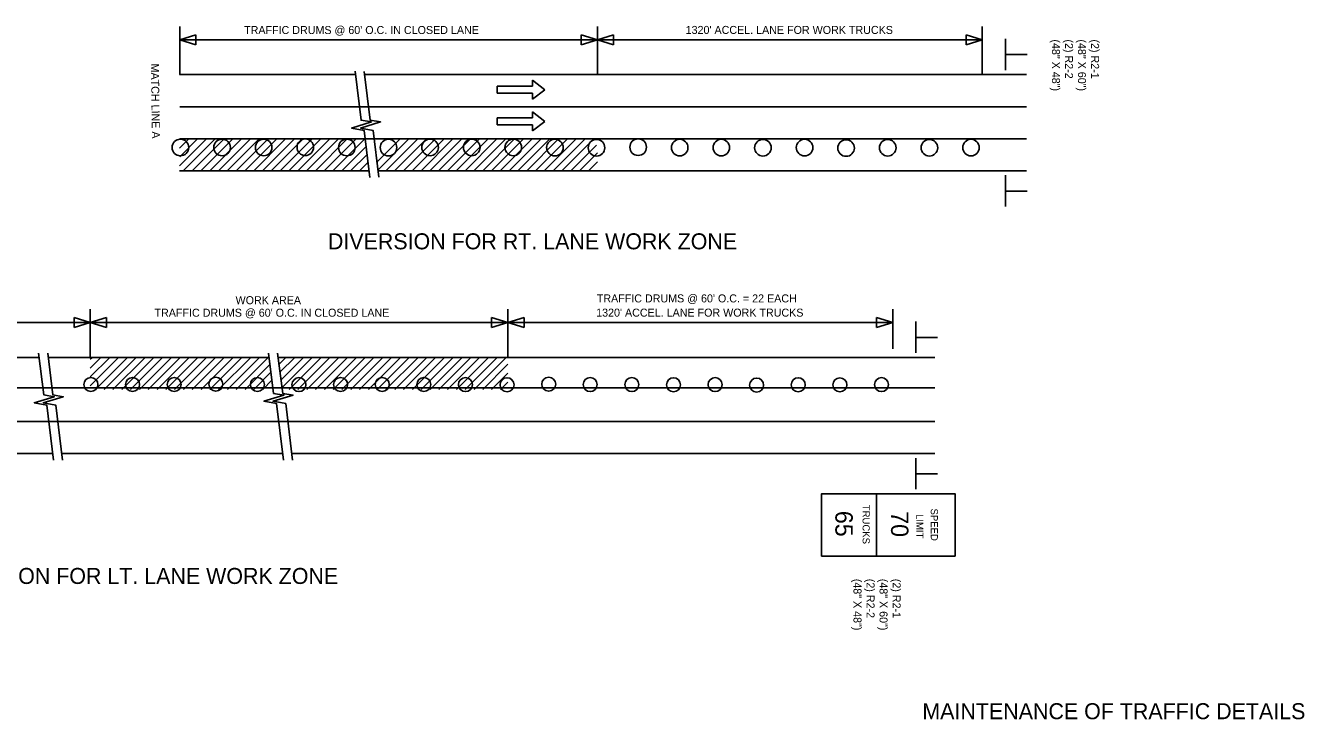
# Model space of a CAD drawing. Extents: x 37171 to 39457, y -18939 to -17445.
# Drawn here: x 38020 to 39457, y -18939 to -18159 of the extents above; entities that cross this region are included whole.
import ezdxf

# ---------------------------------------------------------------- set-up
doc = ezdxf.new("R2010")
doc.units = 0
for name, color, linetype in [('Default', 7, 'Continuous'), ('R_Border', 7, 'Continuous'), ('R_Const Phase 4', 7, 'Continuous'), ('R_Proposed Road Annot', 7, 'Continuous')]:
    doc.layers.add(name, color=color, linetype=linetype)

msp = doc.modelspace()

# ---------------------------------------------------------------- linework, layer by layer
at = {"layer": 'Default'}
for p, q in [((38192.6, -18316.3), (38222.8, -18286.1)), ((38192.7, -18286.5), (38193.1, -18286.1)), ((38192.7, -18296.4), (38203, -18286.1)), ((38192.9, -18306.1), (38212.9, -18286.1)), ((38196.8, -18321.9), (38232.7, -18286.1)), ((38206.7, -18321.9), (38242.6, -18286.1)), ((38216.6, -18321.9), (38252.5, -18286.1)), ((38226.5, -18321.9), (38262.4, -18286.1)), ((38236.4, -18321.9), (38272.3, -18286.1)), ((38246.3, -18321.9), (38282.2, -18286.1)), ((38256.2, -18321.9), (38292.1, -18286.1)), ((38266.1, -18321.9), (38302, -18286.1)), ((38276, -18321.9), (38311.9, -18286.1)), ((38285.9, -18321.9), (38321.8, -18286.1)), ((38295.8, -18321.9), (38331.7, -18286.1)), ((38305.7, -18321.9), (38341.6, -18286.1)), ((38315.6, -18321.9), (38351.5, -18286.1)), ((38325.5, -18321.9), (38361.4, -18286.1)), ((38335.4, -18321.9), (38371.3, -18286.1)), ((38345.3, -18321.9), (38381.2, -18286.1)), ((38355.2, -18321.9), (38391.1, -18286.1)), ((38365.1, -18321.9), (38401.3, -18285.7)), ((38413.9, -18312.7), (38440.6, -18286.1)), ((38415, -18321.6), (38450.5, -18286.1)), ((38424.5, -18321.9), (38460.4, -18286.1)), ((38434.4, -18321.9), (38470.3, -18286.1)), ((38444.3, -18321.9), (38480.2, -18286.1)), ((38454.2, -18321.9), (38490.1, -18286.1)), ((38464.1, -18321.9), (38500, -18286.1)), ((38474, -18321.9), (38509.9, -18286.1)), ((38483.9, -18321.9), (38519.8, -18286.1)), ((38493.8, -18321.9), (38529.7, -18286.1)), ((38503.7, -18321.9), (38539.6, -18286.1)), ((38513.6, -18321.9), (38549.5, -18286.1)), ((38523.5, -18321.9), (38559.4, -18286.1)), ((38533.4, -18321.9), (38569.3, -18286.1)), ((38543.3, -18321.9), (38579.2, -18286.1)), ((38553.2, -18321.9), (38589.1, -18286.1)), ((38563.1, -18321.9), (38599, -18286.1)), ((38573, -18321.9), (38608.9, -18286.1)), ((38582.9, -18321.9), (38618.8, -18286.1)), ((38592.8, -18321.9), (38628.7, -18286.1)), ((38602.7, -18321.9), (38638.6, -18286.1)), ((38612.6, -18321.9), (38648.5, -18286.1)), ((38622.5, -18321.9), (38658.4, -18286.1)), ((38375, -18321.9), (38402.4, -18294.6)), ((38632.4, -18321.9), (38661.3, -18293)), ((38642.3, -18321.9), (38662.4, -18301.8)), ((38384.9, -18321.9), (38403.5, -18303.4)), ((38394.8, -18321.9), (38404.5, -18312.2)), ((38652.2, -18321.9), (38662.4, -18311.8)), ((38092.3, -18563.6), (38124.1, -18531.7)), ((38092.3, -18553.7), (38114.2, -18531.7)), ((38092.3, -18543.8), (38104.3, -18531.7)), ((38092.3, -18533.9), (38094.4, -18531.7)), ((38098, -18567.7), (38134, -18531.7)), ((38107.9, -18567.7), (38143.9, -18531.7)), ((38117.8, -18567.7), (38153.8, -18531.7)), ((38127.7, -18567.7), (38163.7, -18531.7)), ((38137.6, -18567.7), (38173.6, -18531.7)), ((38147.5, -18567.7), (38183.5, -18531.7)), ((38157.4, -18567.7), (38193.4, -18531.7)), ((38167.3, -18567.7), (38203.3, -18531.7)), ((38177.2, -18567.7), (38213.2, -18531.7)), ((38187.1, -18567.7), (38223.1, -18531.7)), ((38197, -18567.7), (38233, -18531.7)), ((38206.9, -18567.7), (38242.9, -18531.7)), ((38216.8, -18567.7), (38252.8, -18531.7)), ((38226.7, -18567.7), (38262.7, -18531.7)), ((38236.6, -18567.7), (38272.6, -18531.7)), ((38246.5, -18567.7), (38282.5, -18531.7)), ((38256.4, -18567.7), (38292.4, -18531.7)), ((38304.5, -18539.4), (38312.2, -18531.7)), ((38305.8, -18548), (38322.1, -18531.7)), ((38306.8, -18556.9), (38332, -18531.7)), ((38307.9, -18565.7), (38341.9, -18531.7)), ((38315.8, -18567.7), (38351.8, -18531.7)), ((38325.7, -18567.7), (38361.7, -18531.7)), ((38335.6, -18567.7), (38371.6, -18531.7)), ((38345.5, -18567.7), (38381.5, -18531.7)), ((38355.4, -18567.7), (38391.4, -18531.7)), ((38365.3, -18567.7), (38401.3, -18531.7)), ((38375.2, -18567.7), (38411.2, -18531.7)), ((38385.1, -18567.7), (38421.1, -18531.7)), ((38395, -18567.7), (38431, -18531.7)), ((38404.9, -18567.7), (38440.9, -18531.7)), ((38414.8, -18567.7), (38450.8, -18531.7)), ((38424.7, -18567.7), (38460.7, -18531.7)), ((38434.6, -18567.7), (38470.6, -18531.7)), ((38444.5, -18567.7), (38480.5, -18531.7)), ((38454.4, -18567.7), (38490.4, -18531.7)), ((38464.3, -18567.7), (38500.3, -18531.7)), ((38474.2, -18567.7), (38510.2, -18531.7)), ((38484.1, -18567.7), (38520.1, -18531.7)), ((38494, -18567.7), (38530, -18531.7)), ((38503.9, -18567.7), (38539.9, -18531.7)), ((38513.8, -18567.7), (38549.8, -18531.7)), ((38523.7, -18567.7), (38559.7, -18531.7)), ((38266.3, -18567.7), (38294.3, -18539.7)), ((38533.6, -18567.7), (38561.7, -18539.5)), ((38276.2, -18567.7), (38295.4, -18548.5)), ((38286.1, -18567.7), (38296.7, -18557.1)), ((38543.5, -18567.9), (38561.7, -18549.6)), ((38553.3, -18567.9), (38561.7, -18559.5))]:
    msp.add_line(p, q, dxfattribs=at)
for points in [[(38976.2, -18755.1), (38914.5, -18755.1), (38914.5, -18685.1), (38976.2, -18685.1)], [(39064.5, -18755.1), (38976.2, -18755.1), (38976.2, -18685.1), (39064.5, -18685.1)]]:
    msp.add_lwpolyline(points, close=True, dxfattribs=at)
for centre, radius in [((38193.6, -18295.7), 9.33), ((38240.4, -18295.7), 9.33), ((38287.2, -18295.7), 9.33), ((38334, -18295.4), 9.33), ((38380.7, -18295.7), 9.33), ((38427.5, -18295.8), 9.33), ((38474.3, -18295.6), 9.33), ((38521.1, -18295.6), 9.33), ((38567.8, -18295.6), 9.33), ((38614.6, -18295.8), 9.33), ((38661.4, -18296), 9.33), ((38708.2, -18295.3), 9.33), ((38754.9, -18295.8), 9.33), ((38801.7, -18295.8), 9.33), ((38848.5, -18296), 9.33), ((38895.3, -18295.8), 9.33), ((38942, -18296.3), 9.33), ((38988.8, -18296), 9.33), ((39035.6, -18296), 9.33), ((39082.4, -18295.8), 9.33), ((38093, -18562.2), 7.87), ((38139.8, -18562.2), 7.87), ((38186.6, -18562.2), 7.87), ((38233.4, -18561.9), 7.87), ((38280.1, -18562.2), 7.87), ((38326.9, -18562.4), 7.87), ((38373.7, -18562.2), 7.87), ((38420.5, -18562.2), 7.87), ((38467.2, -18562.2), 7.87), ((38514, -18562.4), 7.87), ((38560.8, -18562.5), 7.87), ((38607.6, -18561.9), 7.87), ((38654.3, -18562.3), 7.87), ((38701.1, -18562.3), 7.87), ((38747.9, -18562.5), 7.87), ((38794.7, -18562.4), 7.87), ((38841.4, -18562.9), 7.87), ((38888.2, -18562.5), 7.87), ((38935, -18562.6), 7.87), ((38981.8, -18562.4), 7.87)]:
    msp.add_circle(centre, radius, dxfattribs=at)
at = {"layer": 'R_Const Phase 4'}
for p, q in [((39121, -18208.8), (39121, -18173.6)), ((39121.5, -18191.3), (39145.5, -18191.3)), ((38192.6, -18213.8), (38390.4, -18213.8)), ((38400.6, -18213.8), (38662.4, -18213.8)), ((38662.4, -18213.8), (39144.7, -18213.8)), ((38589.3, -18226.7), (38549.8, -18226.7)), ((38549.8, -18226.7), (38549.8, -18234.7)), ((38589.3, -18220), (38589.3, -18226.7)), ((38589.3, -18220), (38603.2, -18230.7)), ((38589.3, -18234.7), (38549.8, -18234.7)), ((38603.2, -18230.7), (38589.3, -18241.5)), ((38589.3, -18234.7), (38589.3, -18241.5)), ((38192.9, -18249.9), (39144.7, -18249.9)), ((38589.3, -18255.5), (38589.3, -18262.2)), ((38589.3, -18255.5), (38603.2, -18266.3)), ((38589.3, -18262.2), (38549.8, -18262.2)), ((38549.8, -18262.2), (38549.8, -18270.3)), ((38589.3, -18270.3), (38549.8, -18270.3)), ((38603.2, -18266.3), (38589.3, -18277)), ((38589.3, -18270.3), (38589.3, -18277)), ((38192.9, -18286.1), (39144.7, -18286.1)), ((38192.6, -18321.9), (38405.7, -18321.9)), ((38415, -18321.9), (38662.4, -18321.9)), ((38662.4, -18321.9), (39144.7, -18321.9)), ((39121, -18362.2), (39121, -18326.9)), ((39121.5, -18344.7), (39145.5, -18344.7)), ((39020.4, -18526.7), (39020.4, -18491.5)), ((39020.9, -18509.2), (39044.9, -18509.2)), ((37659.5, -18531.7), (38034.8, -18531.7)), ((38045, -18531.7), (38092.3, -18531.7)), ((38092.3, -18531.7), (38293.4, -18531.7)), ((38303.6, -18531.7), (38561.7, -18531.7)), ((38561.7, -18531.7), (39041.7, -18531.7)), ((37294.7, -18566), (39041.7, -18566)), ((37294.7, -18603.9), (39041.7, -18603.9)), ((37659.5, -18639.9), (38050, -18639.9)), ((38060.2, -18639.9), (38092.3, -18639.9)), ((38092.3, -18639.9), (38308.6, -18639.9)), ((38318.8, -18639.9), (38561.7, -18639.9)), ((38561.7, -18639.9), (39041.7, -18639.9)), ((39020.4, -18680.1), (39020.4, -18644.9)), ((39020.9, -18662.6), (39044.9, -18662.6))]:
    msp.add_line(p, q, dxfattribs=at)
for points in [[(38389.9, -18209.9), (38396.8, -18265), (38408.4, -18267), (38386, -18273.8), (38400.2, -18276.6), (38406.6, -18329.5)], [(38400.2, -18210.4), (38407, -18265), (38418.6, -18267), (38396.2, -18273.8), (38410.4, -18276.6), (38416.7, -18328.9)], [(38034.2, -18526.8), (38040.1, -18573.9), (38051.7, -18576), (38029.2, -18582.8), (38043.5, -18585.5), (38051, -18647.4)], [(38044.4, -18526.8), (38050.3, -18573.9), (38061.9, -18576), (38039.4, -18582.8), (38053.7, -18585.5), (38061.2, -18647.4)], [(38292.7, -18526.8), (38298.4, -18572.2), (38310, -18574.2), (38287.5, -18581), (38301.8, -18583.7), (38309.5, -18647.4)], [(38302.9, -18526.8), (38308.6, -18572.2), (38320.2, -18574.2), (38297.7, -18581), (38312, -18583.7), (38319.7, -18647.4)]]:
    msp.add_lwpolyline(points, dxfattribs=at)
at = {"layer": 'R_Proposed Road Annot'}
for p, q in [((38192.9, -18159.5), (38192.9, -18213.8)), ((38192.9, -18174.6), (38211.1, -18169.1)), ((38211.1, -18169.1), (38211.1, -18180.1)), ((38644.1, -18180.1), (38644.1, -18169.1)), ((38644.1, -18169.1), (38662.4, -18174.6)), ((38662.4, -18159.5), (38662.4, -18213.8)), ((38662.4, -18174.6), (38680.6, -18169.1)), ((38680.6, -18169.1), (38680.6, -18180.1)), ((39076.8, -18180.1), (39076.8, -18169.1)), ((39076.8, -18169.1), (39095.1, -18174.6)), ((39095.1, -18159.5), (39095.1, -18213.8)), ((38662.4, -18174.6), (38192.9, -18174.6)), ((38211.1, -18180.1), (38192.9, -18174.6)), ((38662.4, -18174.6), (38644.1, -18180.1)), ((39095.1, -18174.6), (38662.4, -18174.6)), ((38680.6, -18180.1), (38662.4, -18174.6)), ((39095.1, -18174.6), (39076.8, -18180.1)), ((38074, -18498), (38074, -18487)), ((38074, -18487), (38092.3, -18492.5)), ((38092.3, -18477.4), (38092.3, -18531.7)), ((38092.3, -18492.5), (38110.5, -18487)), ((38110.5, -18487), (38110.5, -18498)), ((38543.5, -18498), (38543.5, -18487)), ((38543.5, -18487), (38561.7, -18492.5)), ((38561.7, -18477.4), (38561.7, -18531.7)), ((38561.7, -18492.5), (38580, -18487)), ((38580, -18487), (38580, -18498)), ((38976.2, -18498), (38976.2, -18487)), ((38976.2, -18487), (38994.5, -18492.5)), ((38994.5, -18477.4), (38994.5, -18522.1)), ((38092.3, -18492.5), (37659.5, -18492.5)), ((38092.3, -18492.5), (38074, -18498)), ((38561.7, -18492.5), (38092.3, -18492.5)), ((38110.5, -18498), (38092.3, -18492.5)), ((38561.7, -18492.5), (38543.5, -18498)), ((38994.5, -18492.5), (38561.7, -18492.5)), ((38580, -18498), (38561.7, -18492.5)), ((38994.5, -18492.5), (38976.2, -18498))]:
    msp.add_line(p, q, dxfattribs=at)

# ---------------------------------------------------------------- texts
at = {"layer": 'Default'}
for s, height, p in [('TRUCKS', 8.02, (38960.5, -18697.5)), ('SPEED', 8.02, (39037.2, -18701.7)), ('65', 19.54, (38929.9, -18704.3)), ('70', 19.54, (38992.5, -18704.7)), ('LIMIT', 8.02, (39020.8, -18707.9))]:
    msp.add_text(s, height=height, rotation=270, dxfattribs=at).set_placement(p)
at = {"layer": 'R_Border'}
msp.add_text('MAINTENANCE OF TRAFFIC DETAILS', height=18, dxfattribs=at).set_placement((39027.7, -18938.6))
at = {"layer": 'R_Proposed Road Annot'}
for s, height, p in [("TRAFFIC DRUMS @ 60' O.C. IN CLOSED LANE", 9, (38265.2, -18168.1)), ("1320' ACCEL. LANE FOR WORK TRUCKS", 9, (38761.6, -18168)), ('DIVERSION FOR RT. LANE WORK ZONE', 18, (38359.4, -18410.2)), ('WORK AREA', 9, (38255.6, -18471.9)), ("TRAFFIC DRUMS @ 60' O.C. = 22 EACH", 9, (38661.7, -18469.9)), ("TRAFFIC DRUMS @ 60' O.C. IN CLOSED LANE", 9, (38164.5, -18486)), ("1320' ACCEL. LANE FOR WORK TRUCKS", 9, (38661, -18485.9)), ('DIVERSION FOR LT. LANE WORK ZONE', 18, (37914.9, -18786.5))]:
    msp.add_text(s, height=height, dxfattribs=at).set_placement(p)
for s, rotation, p in [('(48" X 48")', 270, (39173.4, -18174.2)), ('(2) R2-2', 270, (39188.1, -18174.2)), ('(48" X 60")', 270, (39202.7, -18174.2)), ('(2) R2-1', 270, (39217.4, -18174.2)), ('MATCH LINE A', 270.8059, (38160.4, -18201.4)), ('(48" X 48")', 270, (38950.3, -18780.7)), ('(2) R2-2', 270, (38965, -18780.7)), ('(48" X 60")', 270, (38979.6, -18780.7)), ('(2) R2-1', 270, (38994.3, -18780.7))]:
    msp.add_text(s, height=9, rotation=rotation, dxfattribs=at).set_placement(p)

doc.saveas('drawing.dxf')
